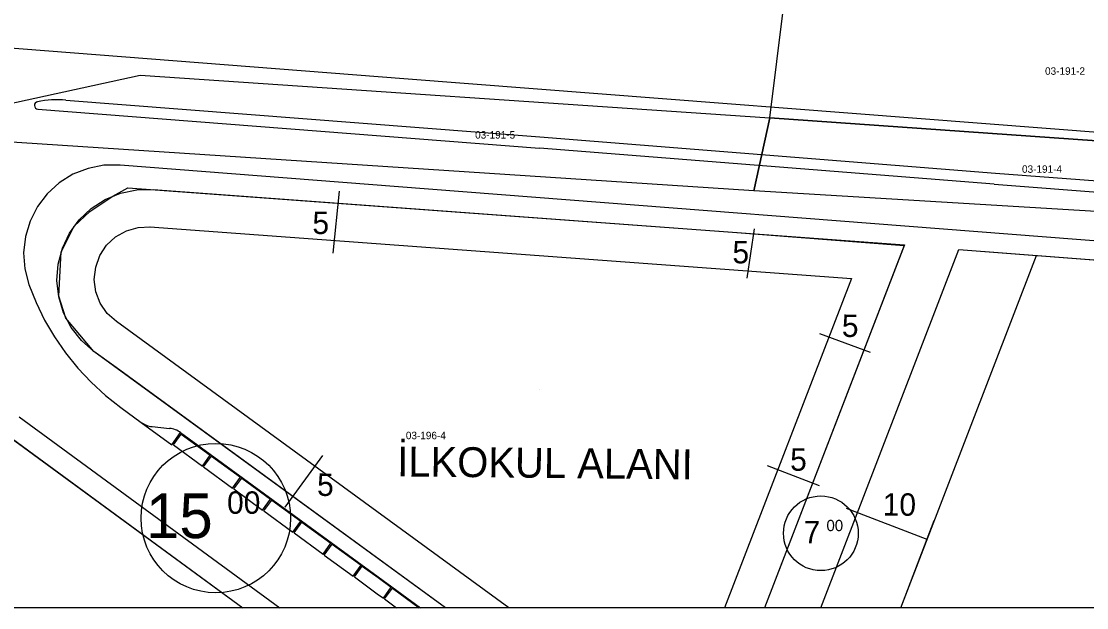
# Model space of a CAD drawing. Extents: x 413946 to 415528, y 4453939 to 4454944.
# Drawn here: x 414109.1 to 414251.7, y 4453939.5 to 4454018 of the extents above; entities that cross this region are included whole.
import ezdxf

# ---------------------------------------------------------------- set-up
doc = ezdxf.new("R2010")
doc.units = 0
for name, color, linetype in [('0_KADASTRO', 7, 'Continuous'), ('0_ÇERÇEVE', 7, 'Continuous'), ('Level 20', 7, 'Continuous'), ('Level 28', 7, 'Continuous'), ('Level 33', 7, 'Continuous'), ('Level 54', 7, 'Continuous'), ('Level 62', 7, 'Continuous'), ('SEMBOL', 7, 'Continuous'), ('SNR_YAPIYAK', 7, 'Continuous')]:
    doc.layers.add(name, color=color, linetype=linetype)

msp = doc.modelspace()

# ---------------------------------------------------------------- linework, layer by layer
at = {"layer": '0_KADASTRO'}
for points in [[(414209.29, 4454005.04), (414211.13, 4454020.13), (414241.63, 4454019.42), (414263.3, 4454018.85), (414276.57, 4454020.48), (414290.75, 4454029.91), (414284.71, 4453999.75)], [(414089.47, 4454002.98), (414125.05, 4454010.74), (414209.29, 4454005.04), (414207.14, 4453995.27)], [(414207.14, 4453995.27), (414209.29, 4454005.04), (414284.71, 4453999.75), (414281, 4453990.83)]]:
    msp.add_lwpolyline(points, close=True, dxfattribs=at)
for points in [[(414165.87, 4453939.48), (414121.81, 4453971.61), (414118.83, 4453973.78), (414115.1, 4453978.25), (414114.16, 4453981.2), (414114.48, 4453987.13), (414116.21, 4453990.54), (414118.3, 4453992.53), (414121.36, 4453994.58), (414123.37, 4453995.7), (414203.68, 4453989.79), (414227.25, 4453987.98), (414208.58, 4453939.48)], [(414083.47, 4453939.48), (414064.21, 4453994.09), (414138.78, 4453939.48)], [(414216.08, 4453939.48), (414234.54, 4453987.42), (414267.68, 4453984.87), (414279.4, 4453980.34), (414274.73, 4453949.8), (414271.84, 4453939.48)], [(414138.78, 4453939.48), (414083.47, 4453939.48)], [(414208.58, 4453939.48), (414165.87, 4453939.48)], [(414271.84, 4453939.48), (414216.08, 4453939.48)]]:
    msp.add_lwpolyline(points, dxfattribs=at)
at = {"layer": '0_ÇERÇEVE'}
msp.add_lwpolyline([(413945.57, 4454943.96), (415494.14, 4454943.96), (415494.14, 4453939.48), (413945.57, 4453939.48)], close=True, dxfattribs=at)
at = {"layer": 'Level 28'}
for p, q in [((414120.36, 4453994.12), (414122.41, 4453994.95)), ((414122.41, 4453994.95), (414124.57, 4453995.4)), ((414124.57, 4453995.4), (414126.78, 4453995.44)), ((414126.78, 4453995.44), (414227.28, 4453988.05)), ((414064.21, 4453994.09), (414138.78, 4453939.48)), ((414116.89, 4453991.4), (414118.5, 4453992.92)), ((414118.5, 4453992.92), (414120.36, 4453994.12)), ((414115.59, 4453989.61), (414116.89, 4453991.4)), ((414114.64, 4453987.61), (414115.59, 4453989.61)), ((414114.07, 4453985.47), (414114.64, 4453987.61)), ((414227.28, 4453988.05), (414208.58, 4453939.48)), ((414216.08, 4453939.48), (414234.54, 4453987.42)), ((414234.54, 4453987.42), (414268.42, 4453984.82)), ((414113.91, 4453983.27), (414114.07, 4453985.47)), ((414114.15, 4453981.07), (414113.91, 4453983.27)), ((414114.79, 4453978.95), (414114.15, 4453981.07)), ((414115.81, 4453976.99), (414114.79, 4453978.95)), ((414117.17, 4453975.24), (414115.81, 4453976.99)), ((414118.83, 4453973.78), (414117.17, 4453975.24)), ((414165.87, 4453939.48), (414118.83, 4453973.78))]:
    msp.add_line(p, q, dxfattribs=at)
at = {"layer": 'Level 54'}
msp.add_line((414178.51, 4453968.62), (414178.51, 4453968.62), dxfattribs=at)
for points in [[(414083.47, 4453939.48), (414064.21, 4453994.09), (414138.78, 4453939.48)], [(414216.08, 4453939.48), (414234.54, 4453987.42), (414268.42, 4453984.82), (414329.47, 4453959.92), (414322.23, 4453939.48)], [(414138.78, 4453939.48), (414083.47, 4453939.48)], [(414322.23, 4453939.48), (414216.08, 4453939.48)]]:
    msp.add_lwpolyline(points, dxfattribs=at)
at = {"layer": 'Level 62'}
for p, q in [((414062.83, 4454017.88), (414160.32, 4454010.32)), ((414160.32, 4454010.32), (414281.9, 4454000.89)), ((414115.1, 4454007.43), (414178.52, 4454002.51)), ((414111.36, 4454006.22), (414178.48, 4454001.01)), ((414178.52, 4454002.51), (414239.47, 4453997.66)), ((414239.29, 4453996.17), (414178.48, 4454001.01)), ((414122.36, 4453998.74), (414159.58, 4453995.85)), ((414239.47, 4453997.66), (414278.78, 4453994.62)), ((414159.58, 4453995.85), (414257.48, 4453988.25)), ((414239.29, 4453996.17), (414255.03, 4453994.95)), ((414122.45, 4453966.28), (414125.17, 4453964.28)), ((414125.17, 4453964.28), (414129.26, 4453961.3)), ((414126.63, 4453963.72), (414128.98, 4453963.48)), ((414129.26, 4453961.3), (414130.44, 4453962.92)), ((414130.44, 4453962.92), (414156.88, 4453943.62)), ((414129.48, 4453961.26), (414130.54, 4453962.72)), ((414130.54, 4453962.72), (414134.42, 4453959.89)), ((414129.48, 4453961.26), (414133.36, 4453958.44)), ((414133.36, 4453958.44), (414134.42, 4453959.89)), ((414133.52, 4453958.32), (414134.58, 4453959.77)), ((414134.58, 4453959.77), (414138.46, 4453956.95)), ((414133.52, 4453958.32), (414137.39, 4453955.49)), ((414137.39, 4453955.49), (414138.46, 4453956.95)), ((414137.56, 4453955.38), (414138.62, 4453956.83)), ((414138.62, 4453956.83), (414142.48, 4453954)), ((414137.56, 4453955.38), (414141.42, 4453952.55)), ((414141.42, 4453952.55), (414142.48, 4453954)), ((414141.58, 4453952.43), (414142.65, 4453953.88)), ((414142.65, 4453953.88), (414146.52, 4453951.05)), ((414141.58, 4453952.43), (414145.46, 4453949.6)), ((414145.46, 4453949.6), (414146.52, 4453951.05)), ((414145.62, 4453949.48), (414146.68, 4453950.93)), ((414146.68, 4453950.93), (414150.56, 4453948.1)), ((414145.62, 4453949.48), (414149.5, 4453946.65)), ((414149.5, 4453946.65), (414150.56, 4453948.1)), ((414149.66, 4453946.53), (414150.72, 4453947.99)), ((414150.72, 4453947.99), (414154.59, 4453945.17)), ((414149.66, 4453946.53), (414153.54, 4453943.71)), ((414153.54, 4453943.71), (414154.59, 4453945.17)), ((414153.7, 4453943.59), (414154.75, 4453945.05)), ((414154.75, 4453945.05), (414156.87, 4453943.5)), ((414153.7, 4453943.59), (414156.76, 4453941.35)), ((414156.87, 4453943.5), (414158.63, 4453942.22)), ((414157.57, 4453940.76), (414158.63, 4453942.22)), ((414157.73, 4453940.65), (414158.79, 4453942.1)), ((414158.79, 4453942.1), (414162.38, 4453939.48)), ((414156.76, 4453941.35), (414157.57, 4453940.76)), ((414157.73, 4453940.65), (414159.33, 4453939.48))]:
    msp.add_line(p, q, dxfattribs=at)
for points in [[(414111.32, 4454007.21), (414111.15, 4454007.15), (414111.01, 4454007.03), (414110.92, 4454006.87), (414110.9, 4454006.69), (414110.94, 4454006.51), (414111.04, 4454006.36), (414111.19, 4454006.26), (414111.37, 4454006.22)], [(414115.1, 4454007.43), (414114.63, 4454007.46), (414114.15, 4454007.47), (414113.67, 4454007.47), (414113.19, 4454007.45), (414112.72, 4454007.41), (414112.24, 4454007.36), (414111.77, 4454007.29), (414111.3, 4454007.21)], [(414122.36, 4453998.73), (414120.19, 4453998.7), (414118.06, 4453998.28), (414116.04, 4453997.49), (414114.2, 4453996.34), (414112.6, 4453994.89), (414111.28, 4453993.16), (414110.3, 4453991.23), (414109.68, 4453989.15), (414109.44, 4453987), (414109.6, 4453984.83), (414110.14, 4453982.73)], [(414110.14, 4453982.73), (414111.11, 4453980.31), (414112.26, 4453977.97), (414113.58, 4453975.72), (414115.06, 4453973.58), (414116.7, 4453971.55), (414118.48, 4453969.65), (414120.4, 4453967.89), (414122.45, 4453966.28)], [(414108.83, 4453965.03), (414143.72, 4453939.48)], [(414125.18, 4453964.28), (414125.34, 4453964.17), (414125.51, 4453964.07), (414125.68, 4453963.99), (414125.87, 4453963.91), (414126.05, 4453963.84), (414126.24, 4453963.79), (414126.44, 4453963.75), (414126.63, 4453963.72)], [(414130.44, 4453962.92), (414130.28, 4453963.03), (414130.11, 4453963.13), (414129.93, 4453963.22), (414129.75, 4453963.29), (414129.56, 4453963.36), (414129.37, 4453963.41), (414129.18, 4453963.45), (414128.98, 4453963.48)], [(414156.88, 4453943.62), (414162.54, 4453939.48)]]:
    msp.add_lwpolyline(points, dxfattribs=at)
at = {"layer": 'SEMBOL'}
for centre, radius in [((414135.16, 4453951.47), 10), ((414216.1, 4453949.44), 5)]:
    msp.add_circle(centre, radius, dxfattribs=at)
at = {"layer": 'SNR_YAPIYAK'}
for p, q in [((414151.68, 4453995.23), (414150.83, 4453986.93)), ((414207.16, 4453990.19), (414206.21, 4453983.57)), ((414215.91, 4453976.2), (414222.7, 4453973.69)), ((414144.43, 4453952.92), (414149.48, 4453959.85)), ((414208.91, 4453958.52), (414215.89, 4453955.82)), ((414230.31, 4453948.61), (414219.54, 4453952.74))]:
    msp.add_line(p, q, dxfattribs=at)
for points in [[(414121.85, 4453977.77), (414121.85, 4453977.77), (414120.62, 4453978.88), (414119.7, 4453980.24), (414119.11, 4453981.78), (414118.9, 4453983.42), (414119.09, 4453985.06), (414119.64, 4453986.61), (414120.55, 4453987.99), (414121.75, 4453989.11), (414123.19, 4453989.93), (414124.77, 4453990.38), (414126.42, 4453990.46)], [(414126.35, 4453990.46), (414220.19, 4453983.56)], [(414226.79, 4453939.48), (414244.95, 4453986.62)], [(414220.19, 4453983.56), (414203.22, 4453939.48)], [(414174.35, 4453939.48), (414121.85, 4453977.77)], [(414226.79, 4453939.48), (414231.28, 4453951.15)]]:
    msp.add_lwpolyline(points, dxfattribs=at)

# ---------------------------------------------------------------- texts
at = {"layer": '0_KADASTRO'}
for s, p in [('03-191-2', (414246.09, 4454010.81)), ('03-191-5', (414169.85, 4454002.27)), ('03-191-4', (414243.01, 4453997.69)), ('03-196-4', (414160.58, 4453962.03))]:
    msp.add_text(s, height=1, dxfattribs=at).set_placement(p)
at = {"layer": 'Level 20'}
for s, p in [('5', (414148.07, 4453989.51)), ('5', (414204.26, 4453985.58)), ('5', (414218.9, 4453975.73)), ('5', (414211.98, 4453957.82)), ('5', (414148.69, 4453954.45)), ('10', (414224.36, 4453951.82))]:
    msp.add_text(s, height=3, rotation=359.4136, dxfattribs=at).set_placement(p)
at = {"layer": 'Level 33'}
msp.add_text('İLKOKUL ALANI', height=4, rotation=359.4136, dxfattribs=at).set_placement((414159.41, 4453957.06))
at = {"layer": 'SEMBOL'}
for s, height, p in [('15', 6, (414125.82, 4453948.79)), ('00', 3, (414136.66, 4453952.05)), ('7', 3, (414213.8, 4453948.1)), ('00', 1.5, (414216.85, 4453949.73))]:
    msp.add_text(s, height=height, dxfattribs=at).set_placement(p)

doc.saveas('drawing.dxf')
